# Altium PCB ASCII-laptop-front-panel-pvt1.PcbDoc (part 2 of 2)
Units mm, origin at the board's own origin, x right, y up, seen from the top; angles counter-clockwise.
Board outline 38.68 x 84.1 mm, 4 copper layers (Top Layer, Internal Plane 1, Internal Plane 2, Bottom Layer), stack 1.573 mm thick; 37 components, 33 nets, 674 pads, 57 vias.
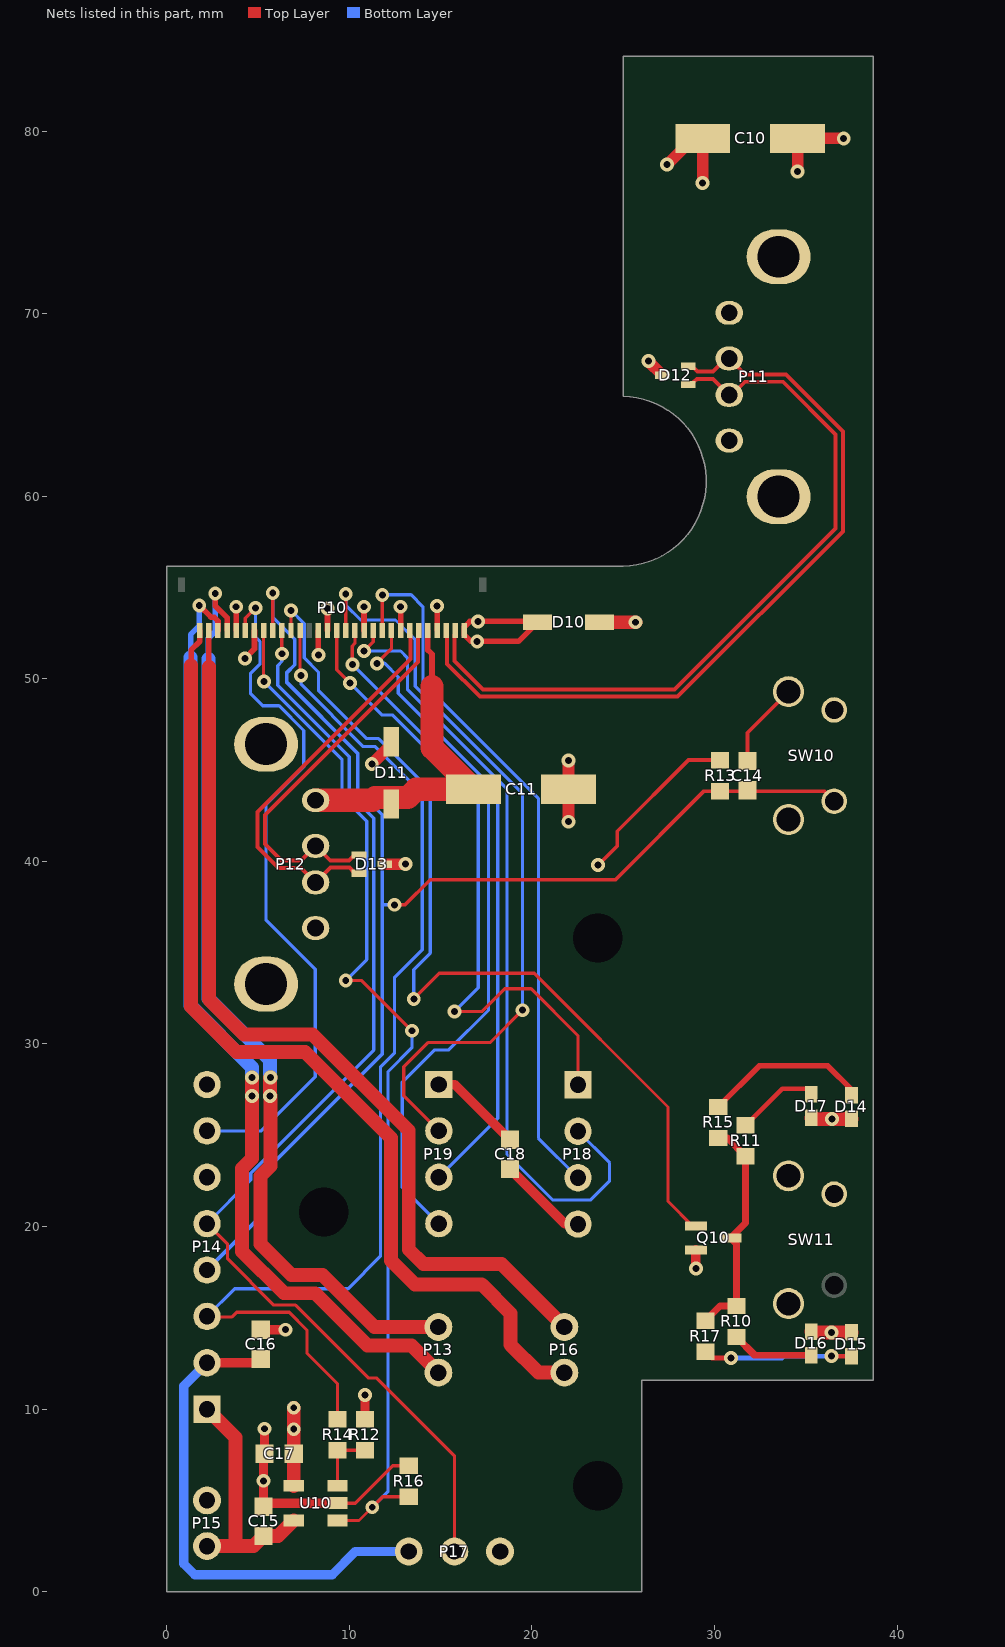
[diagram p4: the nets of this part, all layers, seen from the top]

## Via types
v1: diameter 0.762, hole 0.381, Top Layer to Bottom Layer, tented top, 57 vias

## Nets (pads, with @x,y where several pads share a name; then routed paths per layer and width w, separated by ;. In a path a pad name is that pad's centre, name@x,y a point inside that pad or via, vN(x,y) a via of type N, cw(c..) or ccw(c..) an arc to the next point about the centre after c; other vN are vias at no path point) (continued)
EPIT1_EPITO: P10.8 R16.1 U10.1 | length 58.2
  Top Layer w0.178: P10.8@5.3,52.65 5.3,49.875 v1(5.325,49.85) ; U10.1@9.35,3.9 10.525,3.9 11.825,5.2 R16.1@13.25,5.2 ; v1(9.8,33.475) 10.675,33.475 v1(13.425,30.725)
  Bottom Layer w0.178: v1(5.325,49.85) 9.6,45.575 9.6,43.55 10.95,42.2 10.95,34.625 v1(9.8,33.475) ; v1(11.25,4.625) 12.119,5.494 12.119,28.494 13.425,29.8 v1(13.425,30.725)
FPGA_LSPI_CLK: P10.22 P19.3 | length 34.6
  Top Layer w0.178: v1(11.5,50.85) 12.3,51.65 P10.22@12.3,52.65
  Bottom Layer w0.178: v1(11.5,50.85) 11.925,50.85 12.675,50.1 12.675,49.216 18.125,43.766 18.125,25.925 P19.3@14.9,22.7
FPGA_LSPI_CS: P10.16 P18.1 | length 36
  Top Layer w0.178: P10.16@9.3,52.65 9.3,50.5 v1(10.025,49.775) ; v1(15.75,31.775) 17.25,31.775 18.5,33.025 19.95,33.025 22.52,30.455 P18.1@22.52,27.757
  Bottom Layer w0.178: v1(10.025,49.775) 11.775,48.025 12.35,48.025 17.053,43.322 17.053,33.078 v1(15.75,31.775)
FPGA_LSPI_HOLD: P10.17 P19.2 | length 42
  Top Layer w0.178: P10.17@9.8,52.65 v1(9.8,54.65) ; P19.2@14.9,25.24 12.975,27.165 12.975,28.75 14.3,30.075 17.7,30.075 v1(19.475,31.85)
  Bottom Layer w0.178: v1(9.8,54.65) 9.8,54.034 10.609,53.225 12.525,53.225 13.6,52.15 13.6,49.599 19.475,43.724 v1(19.475,31.85)
FPGA_LSPI_MISO: P10.20 P18.2 | length 43.8
  Top Layer w0.178: v1(10.8,51.525) 11.3,52.025 P10.20@11.3,52.65
  Bottom Layer w0.178: v1(10.8,51.525) 12.8,51.525 13.175,51.15 13.175,49.423 18.625,43.973 18.625,23.975 21.15,21.45 23.2,21.45 24.25,22.5 24.25,23.487 P18.2@22.52,25.217
FPGA_LSPI_MOSI: P10.18 P19.4 | length 38.9
  Top Layer w0.178: v1(10.175,50.775) 10.152,50.798 10.152,51.793 10.3,51.941 P10.18@10.3,52.65
  Bottom Layer w0.178: v1(10.175,50.775) 17.619,43.331 17.619,31.844 15.45,29.675 14.675,29.675 12.9,27.9 12.9,22.16 P19.4@14.9,20.16
FPGA_LSPI_WP: P10.21 P18.3 | length 39.2
  Top Layer w0.178: P10.21@11.8,52.65 v1(11.8,54.6)
  Bottom Layer w0.178: v1(11.8,54.6) 13.375,54.6 14.025,53.95 14.025,49.775 20.35,43.45 20.35,24.847 P18.3@22.52,22.677
GND: C10.2 C11.2 C14.2 C15.2 C16.2 C17.2 C18.2 D10.2 D11.2 D12.3 D13.3 P10.5 P10.19 P10.23 P10.27 P11.0 P11.4 P12.0 P12.4 P14.6 P14.8 P15.1 P17.3 P18.4 Q10.2 R16.2 SW10.0 SW10.2 SW11.0 SW11.2 U10.2 | length 44.1
  Top Layer w0.178: U10.2@9.35,4.85 10.325,4.85 12.375,6.9 R16.2@13.25,6.9
  Top Layer w0.203: C14.2@31.8,45.5 31.8,47.046 SW10.0@34.051,49.296
  Top Layer w0.305: P10.5@3.8,52.65 v1(3.8,53.95) ; P10.19@10.8,52.65 v1(10.8,53.95) ; P10.23@12.8,52.65 v1(12.8,53.95) ; P10.27@14.8,52.65 v1(14.8,54)
  Top Layer w0.508: C16.2@5.15,14.35 v1(6.5,14.35) ; v1(5.35,8.925) C17.2@5.35,7.55 5.3,7.5 C15.2@5.3,4.65 5.5,4.85 U10.2@9.35,4.85 ; C18.2@18.8,23.15 21.813,20.137 P18.4@22.52,20.137 ; v1(28.975,17.7) Q10.2@28.975,18.725
  Top Layer w0.635: v1(11.225,45.325) 12.3,46.4 D11.2@12.3,46.55 ; D13.3@11.925,39.85 v1(13.075,39.85) ; v1(22,42.175) C11.2@22,43.95 v1(22,45.525) ; v1(26.375,67.4) D12.3@27.15,66.625 ; v1(34.55,77.8) C10.2@34.55,79.6 v1(37.075,79.6)
  Top Layer w0.762: D10.2@23.7,53.1 v1(25.675,53.1)
  other v1: 5.3,6.075
GPT_CAPIN1: P10.12 P14.3 R14.2 | length 60.8
  Top Layer w0.178: P14.3@2.2,15.08 2.23,15.05 3.575,15.05 3.825,15.3 6.7,15.3 7.675,14.325 7.675,13.05 9.35,11.375 R14.2@9.35,9.45 ; P10.12@7.3,52.65 7.3,50.225 v1(7.35,50.175)
  Bottom Layer w0.178: P14.3@2.2,15.08 3.72,16.6 9.925,16.6 11.7,18.375 11.7,28.725 12.463,29.488 12.463,33.638 13.988,35.163 13.988,43.712 11.412,46.288 10.762,46.288 7.35,49.7 v1(7.35,50.175)
GPT_CMPOUT3: P10.11 Q10.1 | length 51.1
  Top Layer w0.178: P10.11@6.8,52.65 v1(6.8,53.75) ; v1(13.525,32.475) 14.925,33.875 20.125,33.875 27.45,26.55 27.45,21.375 28.8,20.025 Q10.1@28.975,20.025
  Bottom Layer w0.178: v1(6.8,53.75) 7.525,53.025 7.525,51.15 8.3,50.375 8.3,49.375 10.945,46.73 11.595,46.73 14.43,43.895 14.43,34.98 13.525,34.075 v1(13.525,32.475)
KEY_COL3: P10.10 P14.5 P17.2 | length 63.1
  Top Layer w0.178: P14.5@2.2,20.16 3.325,19.035 3.325,18.225 5.85,15.7 7.05,15.7 11.05,11.7 11.5,11.7 15.75,7.45 P17.2@15.75,2.2 ; v1(6.3,51.375) P10.10@6.3,52.65
  Bottom Layer w0.178: P14.5@2.2,20.16 4.6,22.56 4.6,22.925 11.339,29.664 11.339,42.361 9.989,43.711 9.989,45.736 6.075,49.65 6.075,50.725 6.3,50.95 v1(6.3,51.375)
KEY_ROW1: C14.1 P10.9 P14.4 R13.2 SW10.1 | length 73.5
  Top Layer w0.203: P10.9@5.8,52.65 v1(5.8,54.7) ; v1(12.475,37.625) 13.05,37.625 14.425,39 24.575,39 29.425,43.85 R13.2@30.3,43.85 35.997,43.85 SW10.1@36.551,43.296
  Bottom Layer w0.203: P14.4@2.2,17.62 5.3,20.72 5.3,22.95 11.799,29.449 11.799,37.675 ; v1(5.8,54.7) 5.8,53.375 7,52.175 7,50.775 6.575,50.35 6.575,49.8 10.449,45.926 10.449,43.901 11.799,42.551 11.799,37.675 ; v1(12.475,37.625) 11.849,37.625 11.799,37.675
NetD14_2: D14.2 R15.2 | length 8.8
  Top Layer w0.305: R15.2@30.2,26.55 32.45,28.8 36.2,28.8 D14.2@37.5,27.5
NetD15_2: D15.2 R17.2 | length 8.2
  Top Layer w0.254: R17.2@29.5,13.15 29.85,12.8 v1(30.9,12.8) ; v1(36.4,12.9) D15.2@37.5,12.9
  Bottom Layer w0.254: v1(30.9,12.8) 33.7,12.8 33.8,12.9 v1(36.4,12.9)
NetD16_2: D16.2 R10.2 | length 4.5
  Top Layer w0.381: R10.2@31.2,13.95 32.2,12.95 D16.2@35.3,12.95
NetD17_2: D17.2 R11.2 | length 4.4
  Top Layer w0.25: R11.2@31.7,25.55 33.7,27.55 D17.2@35.3,27.55
NetQ10_3: Q10.3 R10.1 R11.1 R15.1 R17.1 | length 12.6
  Top Layer w0.381: R17.1@29.5,14.85 30.3,15.65 R10.1@31.2,15.65 31.2,19.05 Q10.3@30.875,19.375 31.7,20.2 R11.1@31.7,23.85 30.7,24.85 R15.1@30.2,24.85
P3.3V_DELAYED: C16.1 C18.1 P10.7 P14.2 P17.1 P19.1 R12.1 R13.1 | length 45.4
  Top Layer w0.203: v1(23.625,39.8) 24.675,40.85 24.675,41.65 28.575,45.55 R13.1@30.3,45.55
  Top Layer w0.305: v1(4.275,51.125) 4.8,51.65 P10.7@4.8,52.65
  Top Layer w0.508: P14.2@2.2,12.54 4.94,12.54 C16.1@5.15,12.75 ; R12.1@10.85,9.45 v1(10.85,10.775) ; P19.1@14.9,27.78 15.77,27.78 C18.1@18.8,24.75
  Bottom Layer w0.508: P14.2@2.2,12.54 0.932,11.272 0.932,1.525 1.525,0.932 9.057,0.932 10.325,2.2 P17.1@13.25,2.2
P5.0V_DELAYED: C17.1 D14.1 D15.1 D16.1 D17.1 P10.14 P10.15 U10.4 | length 11.3
  Top Layer w0.305: v1(8.3,51.3) P10.14@8.3,52.65 ; P10.15@8.8,52.65 v1(8.8,53.85)
  Top Layer w0.762: U10.4@6.95,5.8 C17.1@6.95,7.55 v1(6.95,10.075) ; D16.1@35.3,14.25 35.35,14.2 v1(36.4,14.2) D15.1@37.5,14.2 ; D17.1@35.3,25.95 35.35,25.9 D14.1@37.5,25.9
  other v1: 6.95,8.9 36.425,25.9
P5.0V_KBD: C11.1 D11.1 P10.26 P12.1 | length 18.6
  Top Layer w0.305: P10.26@14.3,52.65 14.3,51.575 14.525,51.35 14.525,49.575
  Top Layer w1.27: P12.1@8.15,43.35 11.25,43.35 11.4,43.5 13.2,43.5 13.65,43.95 C11.1@16.8,43.95 14.525,46.225 14.525,49.575
P5.0V_MOUSE: C10.1 D10.1 P10.30 P11.1 | length 14.2
  Top Layer w0.305: P10.30@16.3,52.4 16.65,52.05 v1(17,52.05) 19.25,52.05 D10.1@20.3,53.1 20.25,53.15 v1(17.05,53.15) 16.6,53.15 16.3,52.85 P10.30@16.3,52.65 P10.30@16.3,52.4
  Top Layer w0.635: v1(27.4,78.175) 28.825,79.6 C10.1@29.35,79.6 v1(29.35,77.15)
P5.0V_PEEK: C15.1 P14.1 P15.2 U10.5 | length 13.5
  Top Layer w0.762: P15.2@2.2,2.5 3.75,2.5 ; P14.1@2.2,10 3.75,8.45 3.75,2.5 ; U10.5@6.95,3.9 6.1,3.05 C15.1@5.3,3.05 4.75,2.5 3.75,2.5
PEEK_FLAG: R12.2 R14.1 U10.3 | length 3.5
  Top Layer w0.178: U10.3@9.35,5.8 R14.1@9.35,7.75 R12.2@10.85,7.75
SPK_L_N: P10.3 P13.1 | length 53.6
  Top Layer w0.305: v1(1.775,54.025) 2.42,53.38 2.587,53.38 2.8,53.167 P10.3@2.8,52.65
  Top Layer w0.762: v1(4.675,28.175) v1(4.675,27.15) 4.675,23.725 4.125,23.175 4.125,18.636 6.411,16.349 8.111,16.349 10.986,13.475 13.4,13.475 P13.1@14.875,12
  Bottom Layer w0.305: 1.3,51.175 1.3,52.425 1.775,52.9 v1(1.775,54.025)
  Bottom Layer w0.762: 1.3,51.175 1.3,32.096 4.675,28.721 v1(4.675,28.175) v1(4.675,27.15)
SPK_L_P: P10.4 P13.2 | length 52.4
  Top Layer w0.305: v1(2.65,54.675) 2.65,54 3.3,53.35 P10.4@3.3,52.65
  Top Layer w0.762: v1(5.65,27.15) 5.65,28.15 v1(5.675,28.175) ; v1@5.675,27.15 5.675,23.311 5.125,22.761 5.125,19.05 6.826,17.349 8.526,17.349 11.375,14.5 P13.2@14.875,14.5
  Bottom Layer w0.305: 2.275,51.1 2.275,52.225 2.65,52.6 v1(2.65,54.675)
  Bottom Layer w0.762: 2.275,51.1 2.275,32.5 5.65,29.125 v1(5.65,27.15)
SPK_R_N: P10.1 P16.1 | length 54.5
  Top Layer w0.305: 1.325,50.725 1.325,51.575 1.8,52.05 P10.1@1.8,52.65
  Top Layer w0.762: 1.325,50.725 1.325,32.046 3.821,29.55 7.575,29.55 12.275,24.85 12.275,18.15 13.6,16.825 17.25,16.825 18.825,15.25 18.825,13.525 20.35,12 P16.1@21.775,12
SPK_R_P: P10.2 P16.2 | length 50.9
  Top Layer w0.305: 2.3,50.65 P10.2@2.3,52.65
  Top Layer w0.762: 2.3,50.65 2.3,32.45 4.225,30.525 7.979,30.525 13.25,25.254 13.25,20.925 13.25,18.75 14.05,17.95 18.325,17.95 P16.2@21.775,14.5
TS_ANA: P10.6 P14.7 | length 38.3
  Top Layer w0.178: P10.6@4.3,52.65 4.3,53.325 v1(4.85,53.875)
  Bottom Layer w0.178: P14.7@2.2,25.24 5.165,25.24 8.125,28.2 8.125,34.1 5.425,36.8 5.425,43.1 7.5,45.175 7.5,47.172 6.147,48.525 5.25,48.525 4.575,49.2 4.575,50.275 5.1,50.8 5.1,52.05 4.85,52.3 v1(4.85,53.875)
USB_KBD_N: D13.1 P10.25 P12.2 | length 20.9
  Top Layer w0.216: D13.1@10.225,40.3 9.975,40.05 8.95,40.05 P12.2@8.15,40.85 7.344,40.044 6.288,40.044 5.369,40.963 5.369,42.537 13.75,50.918 P10.25@13.75,52.4
USB_KBD_P: D13.2 P10.24 P12.3 | length 21.6
  Top Layer w0.216: D13.2@10.275,39.375 9.994,39.656 8.956,39.656 P12.3@8.15,38.85 7.35,39.65 6.125,39.65 4.975,40.8 4.975,42.7 13.356,51.081 P10.24@13.356,52.4
USB_MOUSE_N: D12.1 P10.29 P11.2 | length 41.5
  Top Layer w0.216: P10.29@15.75,52.4 15.75,50.975 17.306,49.419 27.812,49.419 36.631,58.238 36.631,63.387 33.743,66.275 31.675,66.275 30.95,65.55 P11.2@30.8,65.55 29.919,66.431 29.031,66.431 D12.1@28.85,66.25
USB_MOUSE_P: D12.2 P10.28 P11.3 | length 43.8
  Top Layer w0.216: P10.28@15.356,52.4 15.356,50.812 17.143,49.025 27.975,49.025 37.025,58.075 37.025,63.55 33.906,66.669 31.681,66.669 P11.3@30.8,67.55 30.65,67.55 29.925,66.825 29.075,66.825 28.75,67.15 D12.2@28.525,67.15
pads on no net: P10.0

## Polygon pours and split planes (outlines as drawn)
GND on Bottom Layer "gnd" (solid, remove dead copper, pour order 2): -5.525,-2.675 42.975,-2.675 53.075,7.425 53.075,75.5 41.375,87.2 16.275,87.2 -6.65,64.275 -6.65,-1.325 -5.225,-2.75
GND on Top Layer "gnd" (solid, remove dead copper, pour order 4): -4.65,27.325 -4.65,1.1 0.325,-3.875 37.1,-3.875 43.925,2.95 43.925,83.925 39.275,88.575 17.575,88.575 -4.65,66.35
GND on Internal Plane 1 (split plane): 38.174,12.091 26,12.091 25.9,12.082 25.805,12.053 25.716,12.005 25.639,11.942 25.576,11.865 25.528,11.776 25.499,11.681 25.49,11.581 25.49,0.51 0.51,0.51 0.51,55.651 24.997,55.651 25.029,55.654 25.193,55.659 25.504,55.687 25.813,55.734 26.119,55.8 26.42,55.883 26.715,55.985 27.004,56.105 27.285,56.242 27.557,56.395 27.819,56.565 28.071,56.75 28.311,56.95 28.538,57.164 28.753,57.392 28.953,57.632 29.138,57.884 29.308,58.146 29.461,58.418 29.598,58.699 29.717,58.988 29.819,59.283 29.903,59.584 29.969,59.89 30.016,60.198 30.044,60.51 30.054,60.822 30.044,61.134 30.016,61.445 29.969,61.754 29.903,62.06 29.819,62.361 29.717,62.656 29.598,62.945 29.461,63.226 29.308,63.498 29.138,63.76 28.953,64.012 28.753,64.252 28.538,64.48 28.311,64.694 28.071,64.894 27.819,65.079 27.557,65.249 27.285,65.402 27.004,65.539 26.715,65.658 26.42,65.76 26.119,65.844 25.813,65.91 25.508,65.956 25.508,82.115 25.508,82.116 25.508,83.589 38.174,83.589
P5.0V_MOUSE on Internal Plane 2 (split plane): 38.174,47.152 16.667,47.152 14.902,48.917 14.902,52.983 15.497,53.578 15.519,53.611 15.527,53.65 15.527,54.45 15.519,54.489 15.497,54.522 14.927,55.092 14.927,55.651 24.997,55.651 25.029,55.654 25.193,55.659 25.504,55.687 25.813,55.734 26.119,55.8 26.42,55.883 26.715,55.985 27.004,56.105 27.285,56.242 27.557,56.395 27.819,56.565 28.071,56.75 28.311,56.95 28.538,57.164 28.753,57.392 28.953,57.632 29.138,57.884 29.308,58.146 29.461,58.418 29.598,58.699 29.717,58.988 29.819,59.283 29.903,59.584 29.969,59.89 30.016,60.198 30.044,60.51 30.054,60.822 30.044,61.134 30.016,61.445 29.969,61.754 29.903,62.06 29.819,62.361 29.717,62.656 29.598,62.945 29.461,63.226 29.308,63.498 29.138,63.76 28.953,64.012 28.753,64.252 28.538,64.48 28.311,64.694 28.071,64.894 27.819,65.079 27.557,65.249 27.285,65.402 27.004,65.539 26.715,65.658 26.42,65.76 26.119,65.844 25.813,65.91 25.508,65.956 25.508,82.115 25.508,82.116 25.508,83.589 38.174,83.589
P5.0V_DELAYED on Internal Plane 2 (split plane): 14.723,55.05 14.731,55.011 14.753,54.978 15.323,54.408 15.323,53.692 14.728,53.097 14.706,53.064 14.698,53.025 14.698,48.875 14.706,48.836 14.728,48.803 16.553,46.978 16.586,46.956 16.625,46.948 38.174,46.948 38.174,12.091 26,12.091 25.9,12.082 25.805,12.053 25.716,12.005 25.639,11.942 25.576,11.865 25.528,11.776 25.499,11.681 25.49,11.581 25.49,0.51 0.51,0.51 0.51,11.173 7.583,11.173 11.228,7.528 11.261,7.506 11.3,7.498 17.55,7.498 17.589,7.506 17.622,7.528 18.597,8.503 18.619,8.536 18.627,8.575 18.627,16.733 20.017,18.123 24.85,18.123 24.889,18.131 24.922,18.153 27.647,20.878 27.669,20.911 27.677,20.95 27.677,37.175 27.669,37.214 27.647,37.247 24.197,40.697 24.164,40.719 24.125,40.727 17.792,40.727 13.272,45.247 10.497,48.022 10.464,48.044 10.425,48.052 8.317,48.052 6.602,49.767 6.602,50.383 7.097,50.878 7.119,50.911 7.127,50.95 7.127,52.083 7.872,52.828 7.894,52.861 7.902,52.9 7.902,53.775 7.894,53.814 7.872,53.847 6.927,54.792 6.927,55.651 14.723,55.651
P3.3V_DELAYED on Internal Plane 2 (split plane): 6.723,54.75 6.731,54.711 6.753,54.678 7.698,53.733 7.698,52.942 6.953,52.197 6.931,52.164 6.923,52.125 6.923,50.992 6.428,50.497 6.406,50.464 6.398,50.425 6.398,49.725 6.406,49.686 6.428,49.653 8.203,47.878 8.236,47.856 8.275,47.848 10.383,47.848 13.128,45.103 17.678,40.553 17.711,40.531 17.75,40.523 24.083,40.523 27.473,37.133 27.473,20.992 24.808,18.327 19.975,18.327 19.936,18.319 19.903,18.297 18.453,16.847 18.431,16.814 18.423,16.775 18.423,8.617 17.508,7.702 11.342,7.702 7.697,11.347 7.664,11.369 7.625,11.377 0.51,11.377 0.51,55.651 6.723,55.651

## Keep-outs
Keep-Out Layer:
  the board outline again, w1

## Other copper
Internal Plane 1 (plane layer: these items are gaps in the copper):
  lines w1.016: 24.997,56.161 ccw(c24.881,60.822) 24.997,65.483 24.997,82.115 ; 24.997,56.161 24.997,56.161 ; 24.997,56.161 0,56.161 0,0 26,0 26,11.581 38.685,11.581 38.685,84.099 24.997,84.099 24.997,82.115 ; 24.997,82.115 24.997,82.115
Internal Plane 2 (plane layer: these items are gaps in the copper):
  lines w0.2: -0.05,11.275 7.625,11.275 11.3,7.6 17.55,7.6 18.525,8.575 18.525,16.775 19.975,18.225 24.85,18.225 27.575,20.95 27.575,37.175 24.125,40.625 17.75,40.625 13.2,45.175 10.425,47.95 8.275,47.95 6.5,49.725 6.5,50.425 7.025,50.95 7.025,52.125 7.8,52.9 7.8,53.775 6.825,54.75 6.825,56.225 ; 14.825,56.225 14.825,55.05 15.425,54.45 15.425,53.65 14.8,53.025 14.8,48.875 16.625,47.05 38.75,47.05
  lines w1.016: 24.997,56.161 ccw(c24.881,60.822) 24.997,65.483 24.997,82.115 ; 24.997,56.161 24.997,56.161 ; 24.997,56.161 0,56.161 0,0 26,0 26,11.581 38.685,11.581 38.685,84.099 24.997,84.099 24.997,82.115 ; 24.997,82.115 24.997,82.115

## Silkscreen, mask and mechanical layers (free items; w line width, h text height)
Top Overlay:
  lines w0.2: 30.34,30.294 ccw(c31.356,30.294) 31.356,29.278 35.928,29.278 ccw(c35.928,30.294) 36.944,30.294 36.944,37.406 ccw(c35.928,37.406) 35.928,38.422 31.207,38.422 ccw(c31.207,37.555) 30.34,37.555 30.34,30.294
  text "Front Panel PVT1-A" at 27.525,52.575 h0.76 r270
  text "(SPK)" at 0.8,50.6 h0.7
  text "(USB)" at 14.3,50.6 h0.7
  text "AUX" at 32.9,46.8 h0.7 r90
  text "Singapore" at 27.55,37.7 h0.76 r270
  text "Designed in" at 28.925,37.7 h0.76 r270
  text "DO NOT APPLY 5V" at 10.6,34.9 h0.8 r270
  text "All I/O are 3.3V-only" at 12.1,34.9 h0.8 r270
  text "10/14" at 27.55,30.375 h0.76 r270
  text "3.3V" at 13.7,29.5 h0.7
  text "GND" at 4,27.4 h0.7
  text "CS" at 24.1,27.3 h0.7
  text "HOLD" at 16.5,26.9 h0.7 r270
  text "ANA" at 4,24.9 h0.7
  text "MISO" at 24.1,24.8 h0.7
  text "CLK" at 16.5,23.6 h0.7 r270
  text "GND" at 4,22.4 h0.7
  text "WP" at 24.1,22.3 h0.7
  text "MOSI" at 16.5,21 h0.7 r270
  text "C3" at 4,19.8 h0.7
  text "GND" at 24.1,19.7 h0.7
  text "POWER" at 32.9,17.6 h0.7 r90
  text "R1" at 4,17.3 h0.7
  text "SPK L" at 17.6,16.8 h0.7 r270
  text "SPK R" at 24.6,16.8 h0.7 r270
  text "CAP1" at 4,15.3 h0.7
  text "+" at 13,14.3 h0.7 r90
  text "+" at 19.9,14.3 h0.7 r90
  text "-" at 13,11.7 h0.7 r90
  text "-" at 19.9,11.7 h0.7 r90
  text "3.3V" at 4.2,11.3 h0.7
  text "5VPEEK" at 4.2,9.7 h0.7
  text "-" at 4.7,4.7 h0.7 r90
  text "LID SW" at 16.1,4.4 h0.7 r90
  text "+" at 13.1,4 h0.7
  text "-" at 18,4 h0.7
  text "+" at 4.7,2.3 h0.7 r90
  text "5V PEEK" at 4.2,0.9 h0.7
Mechanical 1:
  circle w0.01: c26.706,71.25 r0.425
  circle w0.01: c26.706,64.25 r0.425
  circle w0.01: c26.706,47.75 r0.425
  circle w0.01: c26.706,40.75 r0.425
  circle w0.01: c7.5,35.5 r1.4
  circle w0.01: c7.5,7.5 r1.4
  lines w0.01: 20.892,60.742 ccw(c20.775,64.54) 20.892,68.338
  lines w0.2: 3.6,7.5 5,7.5 7.5,7.5 ; 3.6,35.5 5,35.5 7.5,35.5 ; 7.5,3.6 7.5,5 7.5,7.5 ; 7.5,11.4 7.5,10 7.5,7.5 ; 7.5,31.6 7.5,33 7.5,35.5 ; 7.5,39.4 7.5,38 7.5,35.5 ; 11.4,7.5 10,7.5 7.5,7.5 ; 11.4,35.5 10,35.5 7.5,35.5 ; 20.892,60.742 20.892,54.483 0,54.483 0,0 17.7,0 17.7,20.273 34.579,34.538 34.579,84.54 20.892,84.54 20.892,68.338 ; 23.781,40.75 24.206,40.75 26.706,40.75 ; 23.781,47.75 24.206,47.75 26.706,47.75 ; 23.781,64.25 24.206,64.25 26.706,64.25 ; 23.781,71.25 24.206,71.25 26.706,71.25 ; 26.706,37.825 26.706,38.25 26.706,40.75 ; 26.706,43.675 26.706,43.25 26.706,40.75 ; 26.706,44.825 26.706,45.25 26.706,47.75 ; 26.706,50.675 26.706,50.25 26.706,47.75 ; 26.706,61.325 26.706,61.75 26.706,64.25 ; 26.706,67.175 26.706,66.75 26.706,64.25 ; 26.706,68.325 26.706,68.75 26.706,71.25 ; 26.706,74.175 26.706,73.75 26.706,71.25 ; 29.631,40.75 29.206,40.75 26.706,40.75 ; 29.631,47.75 29.206,47.75 26.706,47.75 ; 29.631,64.25 29.206,64.25 26.706,64.25 ; 29.631,71.25 29.206,71.25 26.706,71.25
Mechanical 2:
  drawing of 236 lines, arcs and shapes, not listed
Mechanical 3:
  lines w0.127: 55.777,20.834 57.047,19.564 ; 55.777,75.444 57.047,76.714 ; 58.317,20.834 57.047,19.564 ; 58.317,75.444 57.047,76.714 ; 81.177,23.374 123.087,23.374 ; 81.177,38.614 123.087,38.614 120.547,36.074 ; 81.177,60.204 123.087,60.204 120.547,57.664 ; 81.177,72.904 123.087,72.904 ; 82.447,36.074 84.987,38.614 ; 82.447,57.664 84.987,60.204 ; 83.717,24.644 84.987,23.374 ; 83.717,36.074 86.257,38.614 ; 83.717,38.614 81.177,36.074 123.087,36.074 ; 83.717,57.664 86.257,60.204 ; 83.717,60.204 81.177,57.664 123.087,57.664 ; 83.717,71.634 84.987,72.904 ; 84.987,36.074 87.527,38.614 ; 84.987,57.664 87.527,60.204 ; 86.257,24.644 84.987,23.374 ; 86.257,71.634 84.987,72.904 ; 87.527,36.074 90.067,38.614 ; 87.527,57.664 90.067,60.204 ; 88.797,36.074 91.337,38.614 ; 88.797,57.664 91.337,60.204 ; 90.067,36.074 92.607,38.614 ; 90.067,57.664 92.607,60.204 ; 90.84,74.245 92.11,75.515 ; 92.11,72.975 94.65,75.515 ; 92.607,36.074 95.147,38.614 ; 92.607,57.664 95.147,60.204 ; 93.38,72.975 94.65,74.245 ; 93.38,75.515 90.84,72.975 90.84,75.515 94.65,75.515 ; 93.877,36.074 96.417,38.614 ; 93.877,57.664 96.417,60.204 ; 94.65,72.975 94.65,75.515 ; 95.147,36.074 97.687,38.614 ; 95.147,57.664 97.687,60.204 ; 96.417,36.074 98.957,38.614 ; 96.417,57.664 98.957,60.204 ; 97.44,74.245 98.71,75.515 ; 98.71,72.975 101.25,75.515 ; 98.957,36.074 101.497,38.614 ; 98.957,57.664 101.497,60.204 ; 99.98,72.975 101.25,74.245 ; 99.98,75.515 97.44,72.975 97.44,75.515 101.25,75.515 ; 100.227,36.074 102.767,38.614 ; 100.227,57.664 102.767,60.204 ; 101.25,72.975 101.25,75.515 ; 101.497,36.074 104.037,38.614 ; 101.497,57.664 104.037,60.204 ; 102.767,36.074 105.307,38.614 ; 102.767,57.664 105.307,60.204 ; 105.307,36.074 107.847,38.614 ; 105.307,57.664 107.847,60.204 ; 106.577,36.074 109.117,38.614 ; 106.577,57.664 109.117,60.204 ; 110.387,36.074 112.927,38.614 ; 110.387,57.664 112.927,60.204 ; 111.657,36.074 114.197,38.614 ; 111.657,57.664 114.197,60.204 ; 114.179,74.227 115.449,75.497 ; 114.204,21.982 115.474,23.252 ; 114.204,23.252 114.204,20.712 ; 115.449,72.957 117.989,75.497 ; 115.467,36.074 118.007,38.614 ; 115.467,57.664 118.007,60.204 ; 115.474,20.712 118.014,23.252 118.014,20.712 114.204,20.712 ; 116.719,72.957 117.989,74.227 ; 116.719,75.497 114.179,72.957 114.179,75.497 117.989,75.497 ; 116.737,36.074 119.277,38.614 ; 116.737,57.664 119.277,60.204 ; 116.744,20.712 118.014,21.982 ; 116.744,23.252 114.204,20.712 ; 117.989,72.957 117.989,75.497 ; 118.007,36.074 120.547,38.614 ; 118.007,57.664 120.547,60.204 ; 119.277,36.074 121.817,38.614 ; 119.277,57.664 121.817,60.204 ; 121.817,36.074 123.087,37.344 ; 121.817,57.664 123.087,58.934 ; 57.047,19.564 57.047,76.714 ; 84.987,23.374 84.987,72.904 ; 81.177,37.344 82.447,38.614 81.177,37.344 ; 81.177,58.934 82.447,60.204 81.177,58.934 ; 86.257,36.074 88.797,38.614 86.257,36.074 ; 86.257,57.664 88.797,60.204 86.257,57.664 ; 91.337,36.074 93.877,38.614 91.337,36.074 ; 91.337,57.664 93.877,60.204 91.337,57.664 ; 97.687,36.074 100.227,38.614 97.687,36.074 ; 97.687,57.664 100.227,60.204 97.687,57.664 ; 104.037,36.074 106.577,38.614 104.037,36.074 ; 104.037,57.664 106.577,60.204 104.037,57.664 ; 107.847,36.074 110.387,38.614 107.847,36.074 ; 107.847,57.664 110.387,60.204 107.847,57.664 ; 109.117,36.074 111.657,38.614 109.117,36.074 ; 109.117,57.664 111.657,60.204 109.117,57.664 ; 112.927,36.074 115.467,38.614 112.927,36.074 ; 112.927,57.664 115.467,60.204 112.927,57.664 ; 114.197,36.074 116.737,38.614 114.197,36.074 ; 114.197,57.664 116.737,60.204 114.197,57.664
  lines w0.2: 96,72.957 100.232,68.725 124.25,68.725
  text "Board name: laptop-front-panel PVT rev A" at 69.447,90.744 h1
  text "Contact: bunnie@kosagi.com" at 69.447,88.204 h1
  text "Silk: white" at 95.188,80.797 h0.76
  text "Soldermask: matte black" at 95.063,79.297 h0.76
  text "Material and thickness" at 54.507,79.254 h1.27
  text "Finish: Immersion gold" at 95.063,77.947 h0.76
  text "Plate 0.5 oz" at 69.747,74.174 h0.76
  text "Top-bottom pair" at 84.987,74.174 h0.76 r45
  text "Copper 0.5 oz" at 69.747,72.904 h0.76
  text "Total 1.0 oz" at 69.747,71.38 h0.76
  text "8.5mil width, 7mil space = 90 ohm diff +/- 10%" at 125.609,68.687 h0.76
  text "Prepreg" at 59.587,62.744 h0.76
  text "FR-4 0.165mm" at 69.747,62.744 h0.76
  text "Copper 1 oz" at 69.747,58.934 h0.76
  text "Plane" at 126.897,58.934 h0.76
  text "0.035mm" at 72.795,57.664 h0.76
  text "Core" at 59.587,47.504 h0.76
  text "FR-4 height as needed to meet overall height spec" at 69.747,47.504 h0.76
  text "Overall height: 1.58mm +/-10%" at 55.777,42.424 h0.76 r90
  text "Copper 1 oz" at 69.747,37.344 h0.76
  text "0.035mm" at 72.795,36.074 h0.76
  text "Plane" at 126.897,36.074 h0.76
  text "Prepreg" at 59.587,32.264 h0.76
  text "FR-4 0.165mm" at 69.747,32.264 h0.76
  text "Diff pairs also mirror top side impedance traits" at 125.413,26.573 h0.76
  text "Copper 0.5 oz" at 69.747,22.104 h0.76
  text "Finish: Immersion gold" at 95.138,21.197 h0.76
  text "Plate 0.5 oz" at 69.747,20.834 h0.76
  text "Soldermask: matte black" at 95.013,19.597 h0.76
  text "Total 1.0oz" at 69.906,19.266 h0.76
  text "Silk: white" at 95.138,17.997 h0.76
  text "Mech via: 8 mil hole / 18 mil pad smallest" at 69.597,15.884 h0.76
  text "Route: 4mil / 4mil smallest" at 69.597,13.344 h0.76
